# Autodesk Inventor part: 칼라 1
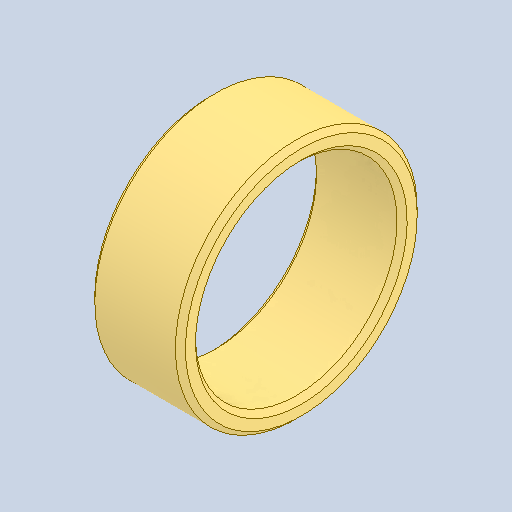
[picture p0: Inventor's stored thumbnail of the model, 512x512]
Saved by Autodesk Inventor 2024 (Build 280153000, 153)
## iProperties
Created: 2025-11
Part Number: 칼라 1
Material: 강철, 연강
Document SubType Name: Modeling
Designer: Eud07
Density: 7.85 g/cm^3
Appearance: 기본값
Author: jhkim
Sending System: Autodesk Inventor 2026
Preprocessor: ST-DEVELOPER v20.1
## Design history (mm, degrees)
node "칼라 11"
node "솔리드2"
node "솔리드1"
